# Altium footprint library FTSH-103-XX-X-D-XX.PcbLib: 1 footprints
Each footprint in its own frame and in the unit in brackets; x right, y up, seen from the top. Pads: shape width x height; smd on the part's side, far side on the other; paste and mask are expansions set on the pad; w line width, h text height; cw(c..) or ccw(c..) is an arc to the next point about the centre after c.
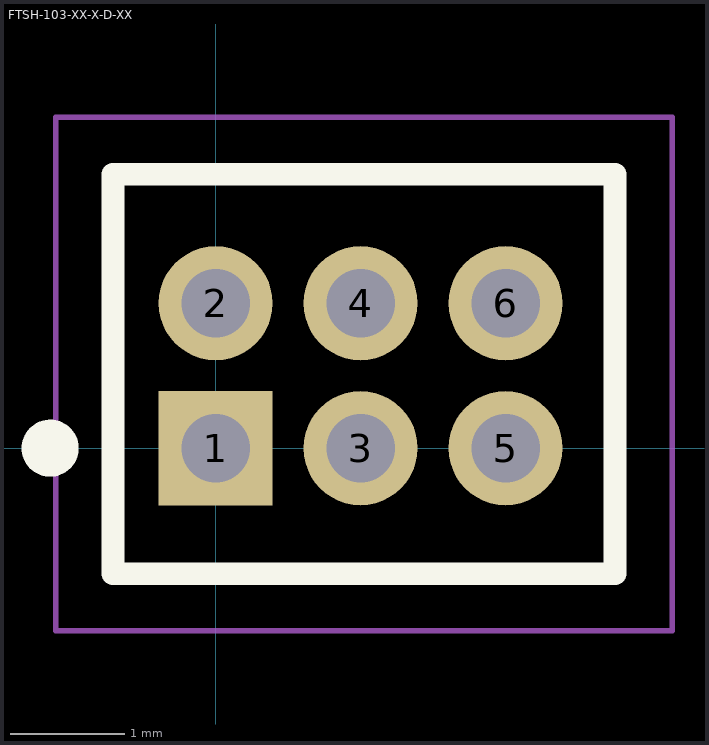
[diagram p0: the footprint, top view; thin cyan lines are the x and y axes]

## FTSH-103-XX-X-D-XX [mm] "1.27mm pitch, 6 pin, interconnect strip; double row"
height 3.05
pads (6):
  rect 1x1 / inner round 1 / far side rect 1x1 hole 0.6 mask+0: 1(0,0)
  round 1 hole 0.6 mask+0: 2(0,1.27) 3(1.27,0) 4(1.27,1.27) 5(2.54,0) 6(2.54,1.27)
Top Overlay:
  circle w0.25: c-1.45,0 r0.125
  lines w0.2: -0.9,-1.1 -0.9,2.4 3.5,2.4 3.5,-1.1 -0.9,-1.1
Mechanical 12:
  lines w0.001: -0.9,-1.1 -0.9,2.4 3.5,2.4 3.5,-1.1 -0.9,-1.1
Mechanical 13:
  circle w0.1: c-1.45,0 r0.125
  lines w0.1: -0.9,-1.1 -0.9,2.4 3.5,2.4 3.5,-1.1 -0.9,-1.1
  text ".Designator" at 0.254,0.254 h1.52
Mechanical 15:
  lines w0.05: -1.4,-1.6 -1.4,2.9 4,2.9 4,-1.6 -1.4,-1.6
